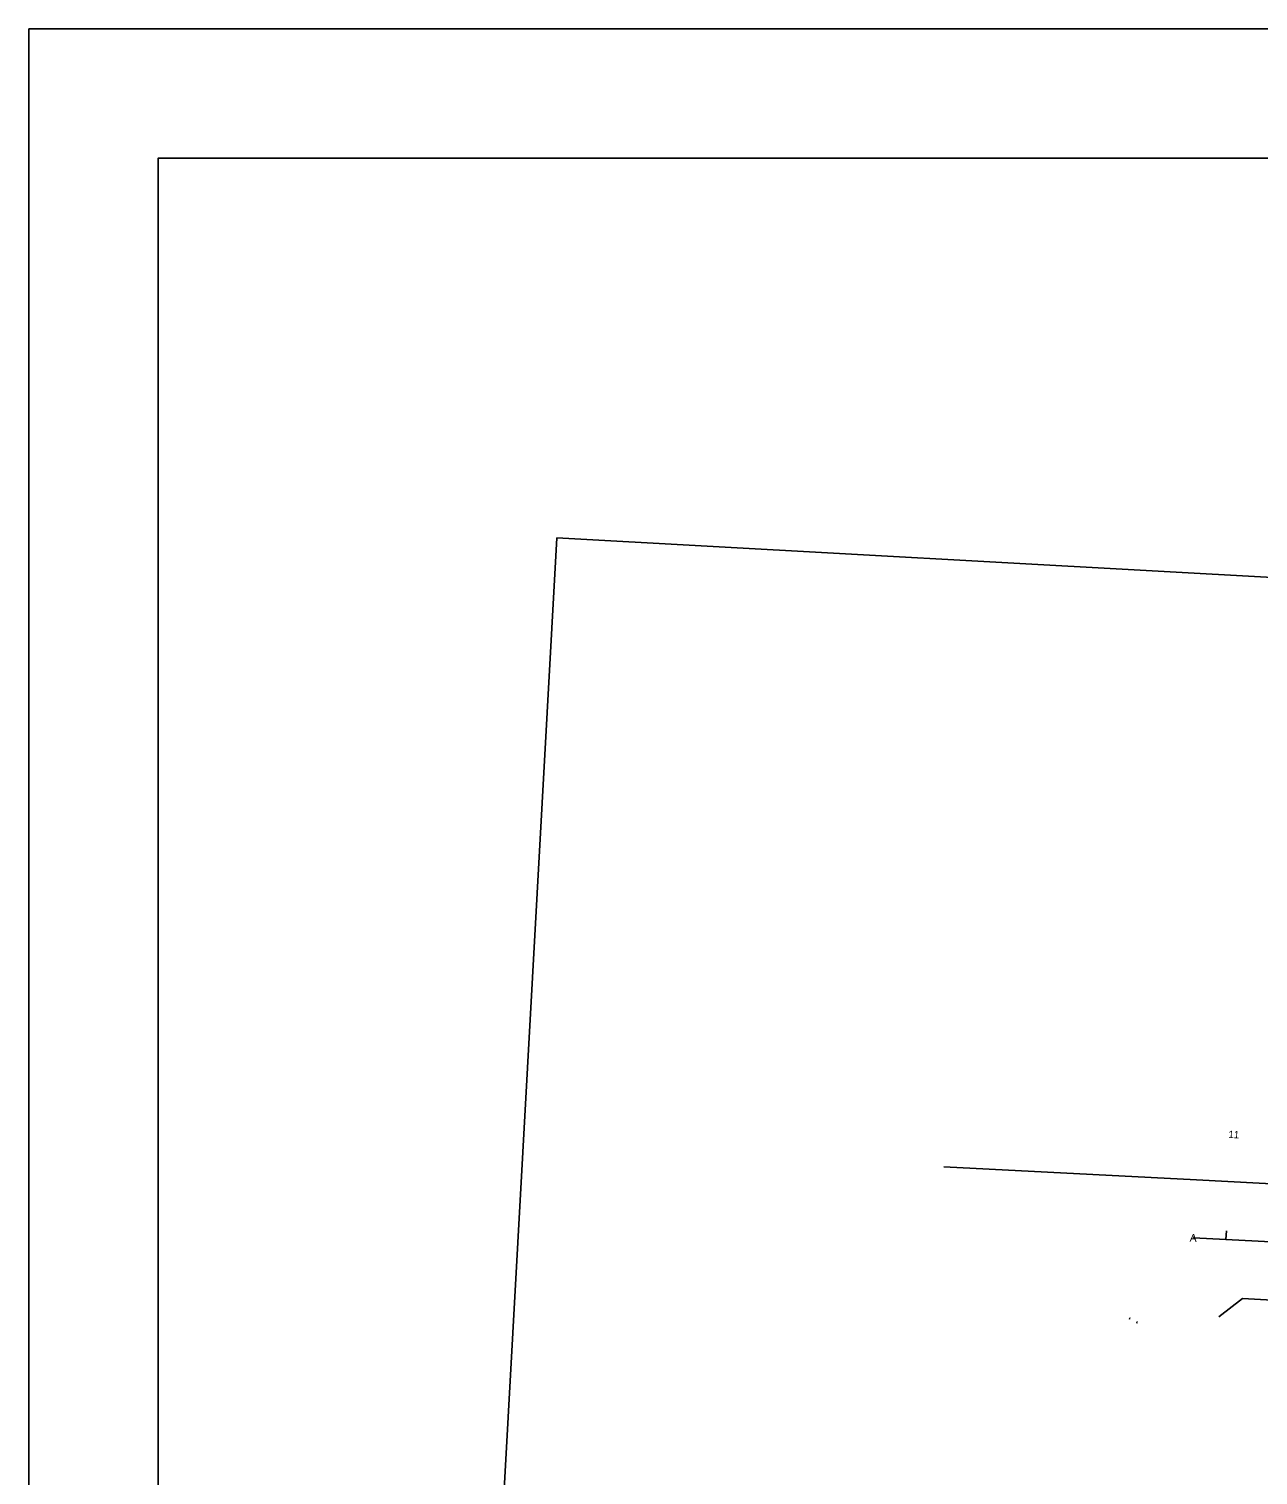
# Model space of a CAD drawing. Extents: x 679444 to 687671, y 733868 to 736107.
# Drawn here: x 679454 to 680405, y 734987 to 736107 of the extents above; entities that cross this region are included whole.
import ezdxf

# ---------------------------------------------------------------- set-up
doc = ezdxf.new("R2010")
doc.units = 0
for name, color, linetype in [('$', 7, 'Continuous'), ('090338 Base_Design base 1-1 - R_Horz Alg', 7, 'Continuous'), ('border All Plan 20-40_Border 1 - Level 1', 7, 'Continuous'), ('C-TOPO', 7, 'Continuous'), ('C-TOPO-FEAT', 7, 'Continuous'), ('R_Horz Alg', 7, 'Continuous'), ('R_Horz Alg Station', 7, 'Continuous'), ('RW-EX', 7, 'Continuous'), ('S_RDW_PT_SYM', 7, 'Continuous'), ('V-NODE', 7, 'Continuous')]:
    doc.layers.add(name, color=color, linetype=linetype)

msp = doc.modelspace()

# ---------------------------------------------------------------- linework, layer by layer
at = {"layer": '$'}
msp.add_lwpolyline([(679553.9, 733968.3), (687571.1, 733968.3), (687571.1, 736006.7), (679553.9, 736006.7), (679553.9, 733968.3)], dxfattribs=at)
at = {"layer": 'border All Plan 20-40_Border 1 - Level 1'}
for p, q in [((679805.6, 734687), (679862.5, 735712.8)), ((679862.5, 735712.8), (681440.9, 735625.3))]:
    msp.add_line(p, q, dxfattribs=at)
at = {"layer": 'C-TOPO'}
msp.add_lwpolyline([(679453.9, 733868.3), (687671.1, 733868.3), (687671.1, 736106.7), (679453.9, 736106.7), (679453.9, 733868.3)], dxfattribs=at)
at = {"layer": 'C-TOPO-FEAT'}
msp.add_lwpolyline([(679553.9, 733968.3), (687571.1, 733968.3), (687571.1, 736006.7), (679553.9, 736006.7), (679553.9, 733968.3)], dxfattribs=at)
at = {"layer": 'R_Horz Alg Station'}
msp.add_line((680355.3, 735171), (680979.5, 735139), dxfattribs=at)
msp.add_lwpolyline([(680380.7, 735176.4), (680380.3, 735169.7)], dxfattribs=at)
at = {"layer": 'RW-EX'}
for p, q in [((680357.6, 735215.9), (680687.4, 735199)), ((680374.9, 735109.9), (680393, 735124)), ((680393, 735124), (680902.3, 735097.9))]:
    msp.add_line(p, q, dxfattribs=at)
msp.add_lwpolyline([(680357.6, 735215.9), (680162, 735226)], dxfattribs=at)
at = {"layer": 'S_RDW_PT_SYM'}
for points in [[(680305.7, 735108.3), (680305.7, 735108.4), (680305.7, 735108.3), (680305.6, 735108.3), (680305.7, 735108.3), (680305.7, 735108.3), (680305.7, 735108.3), (680305.7, 735108.3)], [(680306, 735108.9), (680306, 735108.9), (680306, 735108.9), (680305.9, 735108.9), (680306, 735108.9), (680306, 735108.8), (680306, 735108.9), (680306, 735108.9)], [(680311.4, 735105.3), (680311.4, 735105.3), (680311.4, 735105.3), (680311.3, 735105.3), (680311.4, 735105.3), (680311.4, 735105.2), (680311.4, 735105.3), (680311.4, 735105.3)], [(680311.6, 735105.8), (680311.6, 735105.9), (680311.6, 735105.8), (680311.5, 735105.8), (680311.6, 735105.8), (680311.6, 735105.8), (680311.6, 735105.8), (680311.6, 735105.8)]]:
    msp.add_lwpolyline(points, dxfattribs=at)
at = {"layer": 'V-NODE'}
msp.add_lwpolyline([(679553.9, 733968.3), (687571.1, 733968.3), (687571.1, 736006.7), (679553.9, 736006.7), (679553.9, 733968.3)], dxfattribs=at)

# ---------------------------------------------------------------- texts
at = {"layer": '$'}
msp.add_text('11', height=5.6, rotation=357.065, dxfattribs=at).set_placement((680382.1, 735248.4))
at = {"layer": '090338 Base_Design base 1-1 - R_Horz Alg'}
msp.add_text('A', height=2.4, rotation=357.065, dxfattribs=at).set_placement((680354.1, 735169.9))
at = {"layer": 'R_Horz Alg'}
msp.add_text('A', height=6, rotation=357.065, dxfattribs=at).set_placement((680352.2, 735168.2))

doc.saveas('drawing.dxf')
